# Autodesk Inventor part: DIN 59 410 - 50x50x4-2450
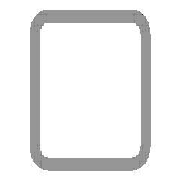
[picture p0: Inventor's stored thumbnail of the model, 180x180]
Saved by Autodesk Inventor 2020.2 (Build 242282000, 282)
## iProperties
Manager: www.cadconsulting.pl
Company: Fabian Stasiak CAD Consulting
Created: 2015-01
Part Number: DIN 59 410 - 50x50x4-2450
Material: Stal, miękka
Description: Rurki stalowe o przekroju kwadratowym formowane na gorąco
Document SubType Name: Modellieren
Standard: DIN
Designer: F.Stasiak
Standards Organization: DIN
Language: pl-PL
Size Designation: 50x50x4
Categories: <MemberInstance><Categories><Category DisplayName="Kształtowniki konstrukcyjne" InternalName="089c4875-fa83-4c05-b084-43b9cc11f5ed" Mnemonic="GRDR"><CategoryPar
Stock Number: 50x50x4
Density: 7.85 g/cm^3
Appearance: Częściowo polerowana
Mass: 13362.7 g
Surface Area: 8525.15 cm^2
Volume: 1702.25 cm^3
Catalog Web Link: www.expertbooks.pl
_CCFamilyMember: 40
_CCFamilyDisplayName: DIN 59410 (Kwadrat) - Rurki stalowe o przekroju kwadratowym formowane na gorąco
_FrameMemberDoc: Frame Member File
_Version: 15.0.0
_GetPNFromCC: 1
G_W: 50,000 mm
G_H: 50,000 mm
+4189659E-D453-45D2-88CD-D273127D69D8+CUTDETAIL1: Wytnij
+17AB2E0B-67E3-4892-95FC-60B82E2690F2+CUTDETAIL2: Wytnij
G_L: 2450,000 mm
IsCustomPart: 1
Author: F.Stasiak
Subject: Zbiór ćwiczeń. Autodesk Inventor 2020. Kurs Professional
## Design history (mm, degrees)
node "Płaszczyzna początkowa"
node "Płaszczyzna końcowa"
sketch "Szkic"
  geometry: L1 (-17, 25)-(17, 25); L2 (25, 17)-(25, -17); L3 (17, -25)-(-17, -25); L4 (-25, -17)-(-25, 17); L5 (-37.32, 0)-(37.32, 0) reference; L6 (0, -37.32)-(0, 37.32) reference; L7 (-17, 21)-(17, 21); L8 (21, 17)-(21, -17); L9 (17, -21)-(-17, -21); L10 (-21, -17)-(-21, 17); A1 r 8 centre (-17, 17) between (-17, 25) and (-25, 17); A2 r 8 centre (17, 17) between (25, 17) and (17, 25); A3 r 8 centre (17, -17) between (17, -25) and (25, -17); A4 r 8 centre (-17, -17) between (-25, -17) and (-17, -25); A5 r 4 centre (-17, 17) between (-17, 21) and (-21, 17); A6 r 4 centre (17, 17) between (21, 17) and (17, 21); A7 r 4 centre (17, -17) between (17, -21) and (21, -17); A8 r 4 centre (-17, -17) between (-21, -17) and (-17, -21); 3 further points
  constraints: 16 end point, 16 point on circle, 8 centre point, 8 tangent, 6 point on line, 4 parallel, 3 equal radius, 3 perpendicular, 1 horizontal, 7 other
  dimensions: "b" = 50 distance of point (-25, 25) point (25, 25); "msp_r" = 8 radius of A1 (= 2 x ParT); "d8" = 25 distance between parallel lines of L4 L6 (= d9); "d9" = 25 distance between parallel lines of L3 L5 (= 0.5 x b); "d10" = 4 distance between parallel lines of L3 L9 (= ParT)
extrude "Bryła" new body sketch "Szkic" taper "d4" = 0 deg; stored distance "NLG" = 10
node "Driven Length"
  sketch "Sketch2"
    geometry: L1 (0, 0)-(10, 0) reference
    constraints: 2 end point, 1 horizontal
  workplane "Work Plane3"
  sketch "Sketch3"
    geometry: L1 (-2, 25)-(12, 25) reference; L2 (-2, 2475)-(12, 2475) reference
    dimensions: "d14" = 2450 distance between parallel lines of L1 L2 (derived)
node "Płaszczyzna konstrukcyjna4"
feature "Podział1"
node "Płaszczyzna konstrukcyjna5"
feature "Podział2"
body "Solid1"
other parameters: "ParT" = 4, "G_OFFSET_START" = -25 [user parameter; used in 1 equation term], "G_OFFSET_END" = -25 [user parameter; used in 1 equation term], "d11" = 25 (= -G_OFFSET_START), "d12" = 2475 (= G_OFFSET_END + B_L), "G_L" = 2450 (= d14) [user parameter], "d13" = 90 deg
